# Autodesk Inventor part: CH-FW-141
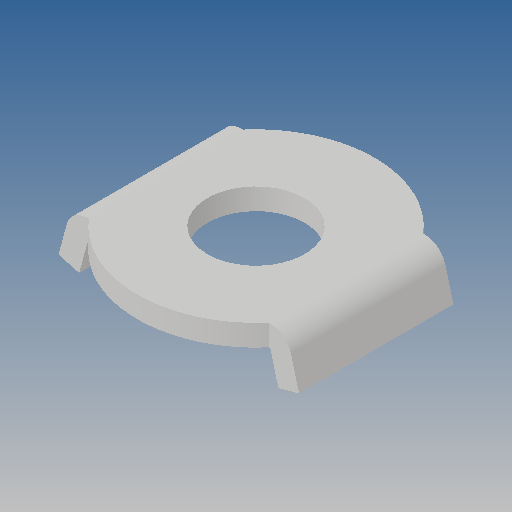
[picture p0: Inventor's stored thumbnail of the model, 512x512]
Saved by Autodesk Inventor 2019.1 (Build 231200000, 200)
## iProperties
Created: 2017-10
Part Number: CH-FW-141
Material: Ogólny
Document SubType Name: Modeling
Designer: CADENGINEERING4
Density: 1 g/cm^3
Appearance: Domyślna
Author: CADENGINEERING4
Revision Number: ÈÎºÎ
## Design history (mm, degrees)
feature "ÇÐ³ý-À­Éì1"
node "Bryła1"
